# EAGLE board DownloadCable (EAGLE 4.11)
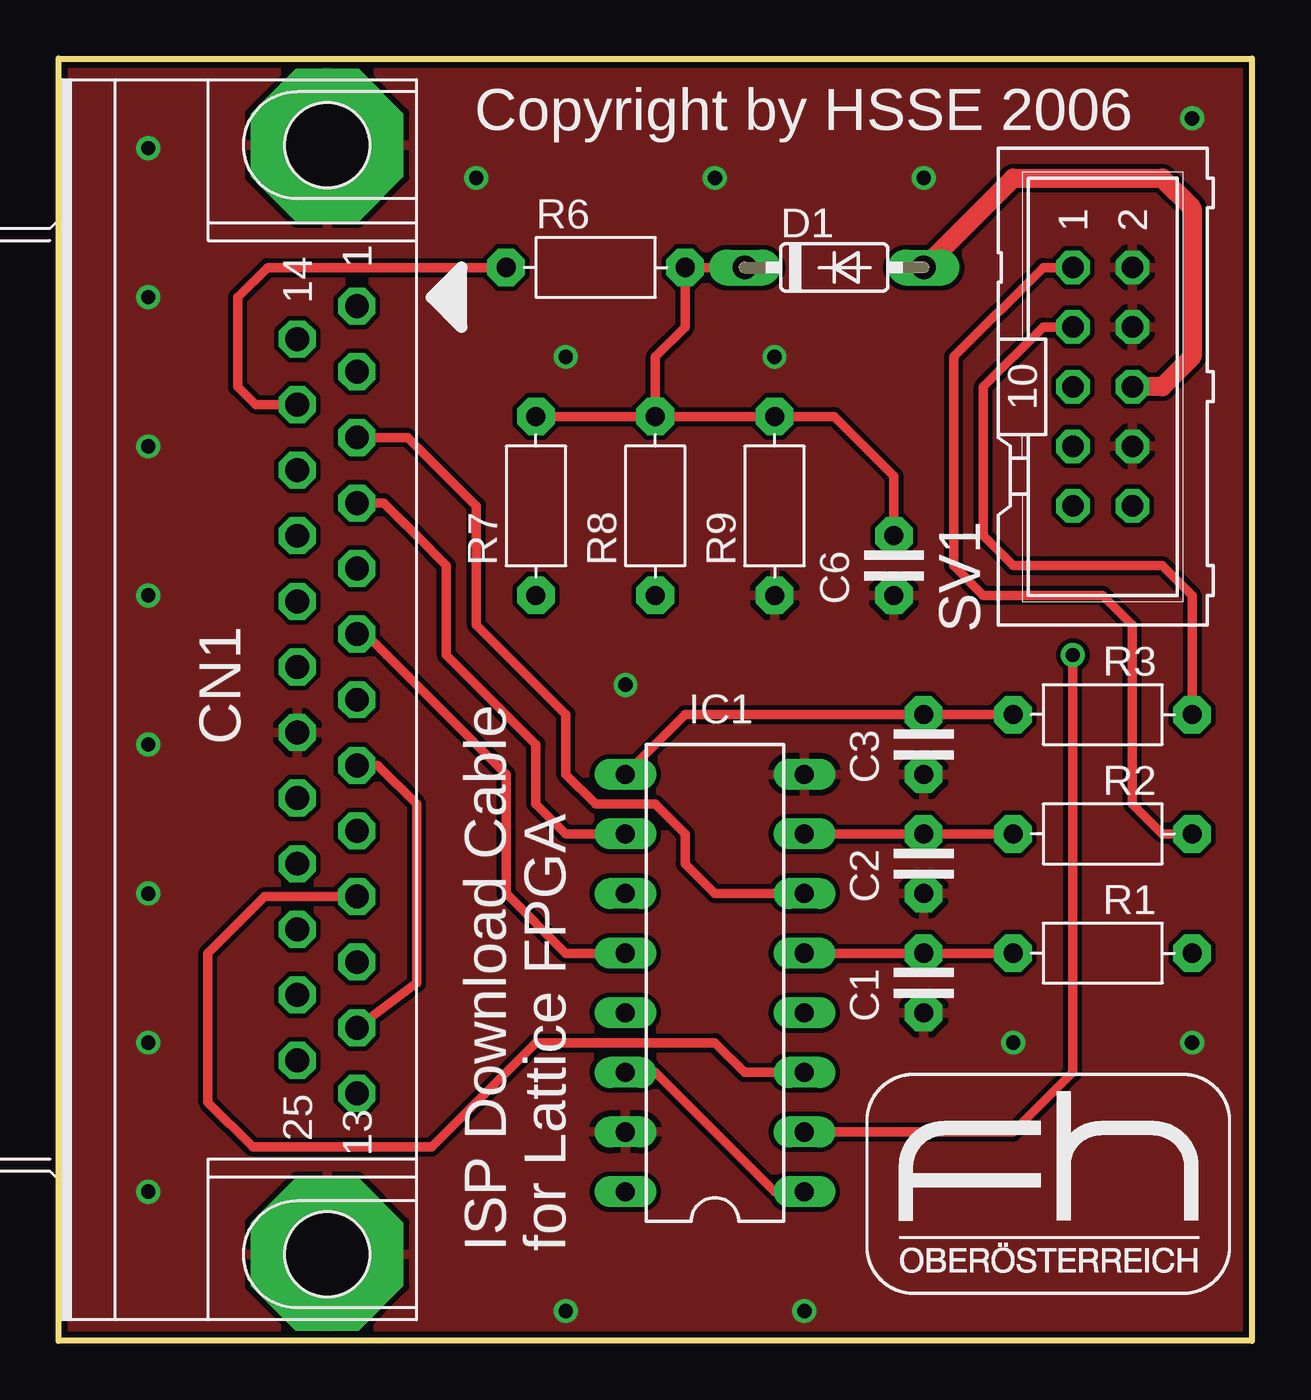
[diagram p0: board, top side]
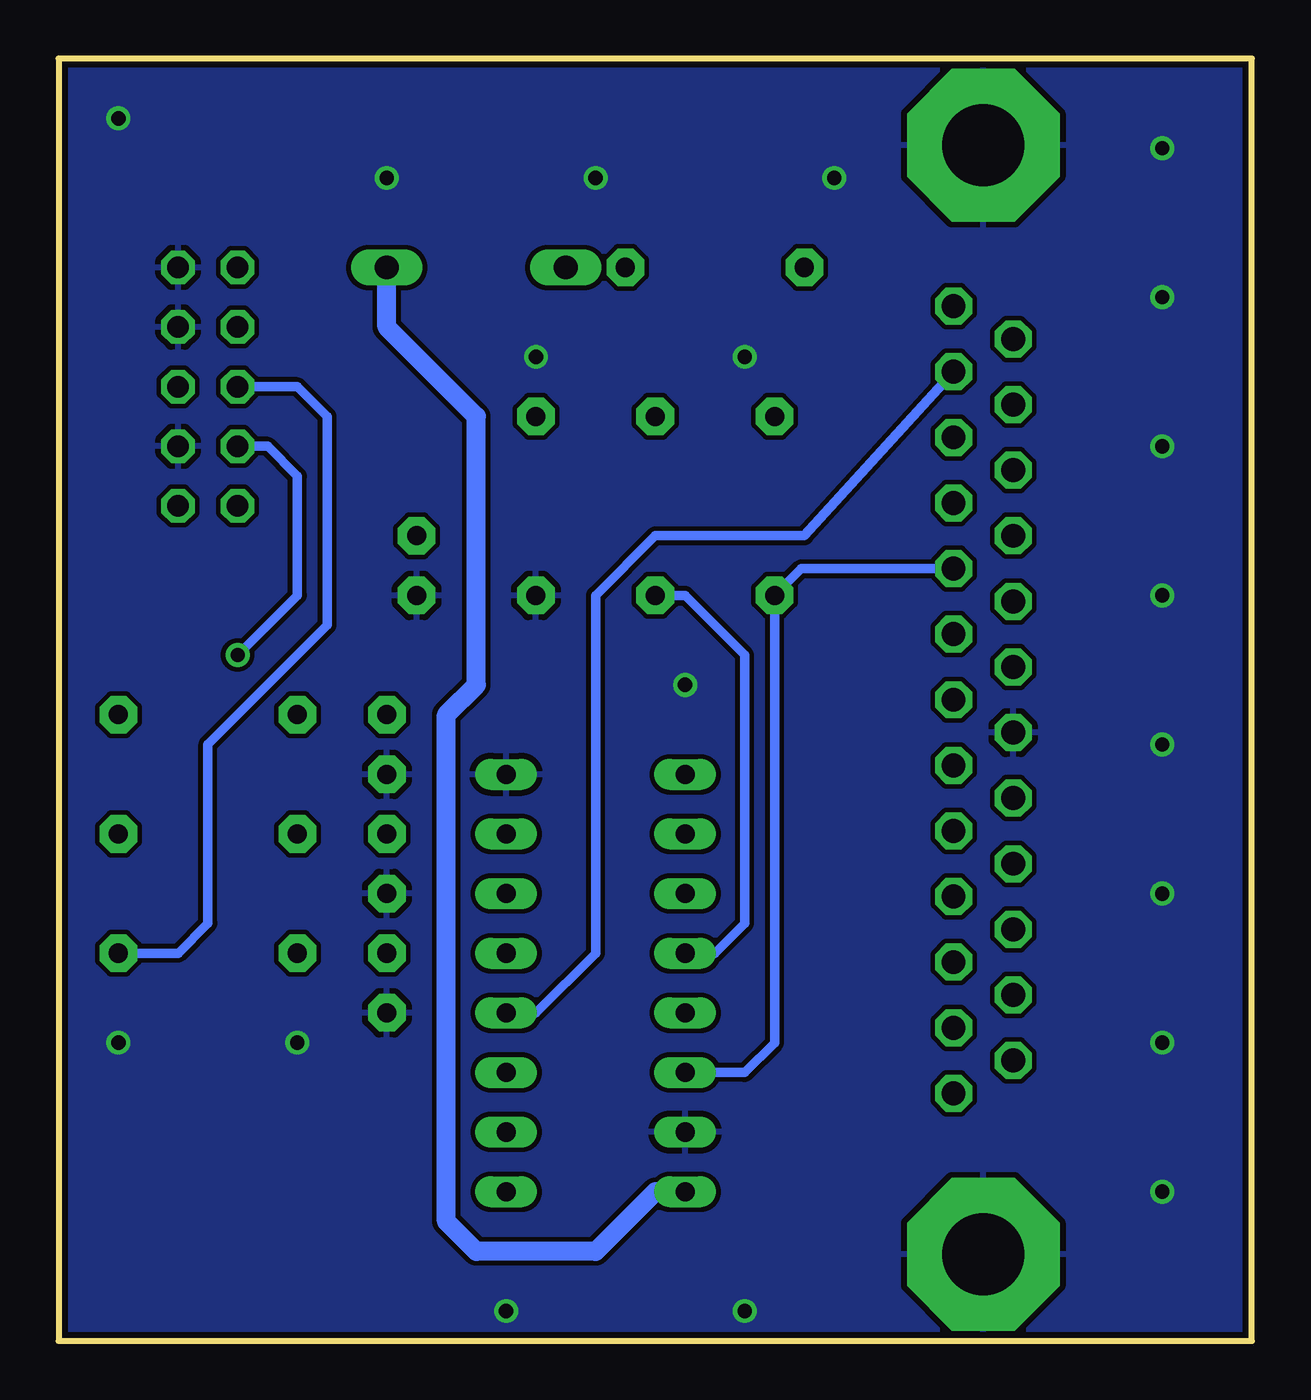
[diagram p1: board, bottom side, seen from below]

Size 50.8 x 54.61 mm. Coordinates in mm from the lower left corner, seen from the top.
Outline: 0,0 0,54.61 50.8,54.61 50.8,0 0,0
Copper layers (1*16): Top 0.035mm / dielectric 1.5mm / Bottom 0.035mm
Design rules "default": minimum track width 10mil, minimum drill 24mil, track to track 8mil, track to pad 8mil, pad to pad 8mil, via to via 8mil, smd to smd 0mil, copper to edge 10mil, drill to drill 8mil, minimum pad ring 10mil, minimum via ring 8mil, stop-mask expansion 4mil, vias tented up to drill 0mil, thermal gap 10mil

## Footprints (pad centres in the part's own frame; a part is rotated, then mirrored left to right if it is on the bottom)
C-2,5 = drill 0.813 pad 1.6 octagon: 1 -1.27,0; 2 1.27,0
D_25M/90 = drill 1.016 pad 1.575 octagon: 1 16.764,-1.27; 2 13.97,-1.27; 3 11.176,-1.27; 4 8.382,-1.27; 5 5.588,-1.27; 6 2.794,-1.27; 7 0,-1.27; 8 -2.794,-1.27; 9 -5.588,-1.27; 10 -8.382,-1.27; 11 -11.176,-1.27; 12 -13.97,-1.27; 13 -16.764,-1.27; 14 15.367,1.27; 15 12.573,1.27; 16 9.779,1.27; 17 6.985,1.27; 18 4.191,1.27; 19 1.397,1.27; 20 -1.397,1.27; 21 -4.191,1.27; 22 -6.985,1.27; 23 -9.779,1.27; 24 -12.573,1.27; 25 -15.367,1.27 | drill 3.5 pad 6.5 octagon: P$1 -23.622,0; P$2 23.622,0
DO35-7 = drill 1.016 long: A 3.81,0; C -3.81,0
DIL16 = drill 0.813 long: 1 -8.89,-3.81; 2 -6.35,-3.81; 3 -3.81,-3.81; 4 -1.27,-3.81; 5 1.27,-3.81; 6 3.81,-3.81; 7 6.35,-3.81; 8 8.89,-3.81; 9 8.89,3.81; 10 6.35,3.81; 11 3.81,3.81; 12 1.27,3.81; 13 -1.27,3.81; 14 -3.81,3.81; 15 -6.35,3.81; 16 -8.89,3.81
R-7,5 = drill 0.813 pad 1.6 octagon: 1 -3.81,0; 2 3.81,0
ML10 = drill 0.914 octagon: 1 -5.08,-1.27; 2 -5.08,1.27; 3 -2.54,-1.27; 4 -2.54,1.27; 5 0,-1.27; 6 0,1.27; 7 2.54,-1.27; 8 2.54,1.27; 9 5.08,-1.27; 10 5.08,1.27

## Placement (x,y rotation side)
C1  560p  [C-2,5]  36.83,15.24 270 top
C2  560p  [C-2,5]  36.83,20.32 270 top
C3  560p  [C-2,5]  36.83,25.4 270 top
C6  100n  [C-2,5]  35.56,33.02 270 top
CN1  [D_25M/90]  11.43,27.3 90 top
D1  [DO35-7]  33.02,45.72 0 top
IC1  74HC367N  [DIL16]  27.94,15.24 90 top
R1  100R  [R-7,5]  44.45,16.51 0 top
R2  100R  [R-7,5]  44.45,21.59 0 top
R3  100R  [R-7,5]  44.45,26.67 0 top
R6  220R  [R-7,5]  22.86,45.72 0 top
R7  10k  [R-7,5]  20.32,35.56 90 top
R8  10k  [R-7,5]  25.4,35.56 90 top
R9  1k  [R-7,5]  30.48,35.56 90 top
SV1  [ML10]  44.45,40.64 270 top

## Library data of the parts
C1-C3 C6 R1-R3 R6-R9 = discrete
CN1 = Con-pc2
D1 = diode
IC1 = 74xx-eu
SV1 = con-harting-ml

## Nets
+3V3: D1.A IC1.16 SV1.6
GND: C1.2 C2.2 C3.2 C6.2 CN1.20 CN1.P$1 CN1.P$2 IC1.8 IC1.15 R9.1 SV1.2 SV1.4 SV1.8
N$1: C6.1 D1.C R6.2 R7.2 R8.2 R9.2
N$2: CN1.10 IC1.3
N$3: CN1.8 CN1.12
N$4: CN1.2 IC1.4
N$5: CN1.6 IC1.12 R8.1
N$6: CN1.5 IC1.1 IC1.14 R7.1
N$7: CN1.3 IC1.6
N$8: CN1.4 IC1.10
N$9: CN1.15 R6.1
N$11: C1.1 IC1.5 R1.1
N$12: C2.1 IC1.7 R2.1
N$13: C3.1 IC1.9 R3.1
TCK: R2.2 SV1.1
TDI: R1.2 SV1.5
TDO: IC1.2 SV1.7
TMS: R3.2 SV1.3

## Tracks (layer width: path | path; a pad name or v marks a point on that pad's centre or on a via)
+3V3
  Top 0.813: SV1.6 46.99,40.64 48.26,41.91 48.26,48.26 46.99,49.53 40.64,49.53 D1.A
  Bottom 0.813: IC1.16 25.4,6.35 27.94,3.81 33.02,3.81 34.29,5.08 34.29,26.67 33.02,27.94 33.02,39.37 36.83,43.18 D1.A
GND  (via drill 0.61)
  other vias: 3.81,50.8 3.81,44.45 3.81,38.1 3.81,31.75 3.81,25.4 3.81,19.05 3.81,12.7 3.81,6.35 21.59,1.27 31.75,1.27 48.26,12.7 40.64,12.7 36.83,49.53 27.94,49.53 17.78,49.53 21.59,41.91 30.48,41.91 24.13,27.94 48.26,52.07
  pour Top: 0,0 0,54.61 50.8,54.61 50.8,0
  pour Bottom: 0,0 0,54.61 50.8,54.61 50.8,0
N$1
  Top 0.406: D1.C R6.2 26.67,43.18 25.4,41.91 R8.2 | C6.1 35.56,36.83 33.02,39.37 R9.2 R8.2 | R7.2 R8.2
N$2
  Top 0.406: IC1.3 29.21,11.43 27.94,12.7 20.32,12.7 15.88,8.26 8.26,8.26 6.35,10.16 6.35,16.51 7.62,17.78 | 7.62,17.78 8.13,18.29 | CN1.10 8.76,18.92 7.62,17.78
N$3
  Top 0.406: CN1.12 15.24,15.24 15.24,21.59 15.24,22.86 13.59,24.51 CN1.8
N$4
  Bottom 0.406: IC1.4 30.48,13.97 27.94,16.51 27.94,31.75 25.4,34.29 19.05,34.29 CN1.2
N$5
  Top 0.406: IC1.12 21.59,16.51 19.05,19.05 19.05,24.13 13.97,29.21 | 13.97,29.21 13.72,29.46 | CN1.6 13.08,30.1 13.97,29.21
  Bottom 0.406: R8.1 24.13,31.75 21.59,29.21 21.59,17.78 22.86,16.51 IC1.12
N$6
  Top 0.406: IC1.1 30.48,6.35 25.4,11.43 IC1.14
  Bottom 0.406: R7.1 19.81,32.26 | IC1.14 21.59,11.43 20.32,12.7 R7.1 | CN1.5 19.18,32.89 R7.1
N$7
  Top 0.406: IC1.6 27.94,19.05 26.67,20.32 26.67,21.59 25.4,22.86 22.86,22.86 21.59,24.13 21.59,26.67 17.78,30.48 17.78,35.56 14.86,38.48 CN1.3
N$8
  Top 0.406: IC1.10 21.59,21.59 20.32,22.86 20.32,25.4 16.51,29.21 16.51,33.02 15.24,34.29 | 15.24,34.29 14.48,35.05 | CN1.4 13.84,35.69 15.24,34.29
N$9
  Top 0.406: R6.1 8.89,45.72 7.62,44.45 7.62,40.64 8.38,39.88 CN1.15
N$11
  Top 0.406: IC1.5 C1.1 R1.1
N$12
  Top 0.406: IC1.7 C2.1 R2.1
N$13
  Top 0.406: IC1.9 26.67,26.67 C3.1 R3.1
TCK
  Top 0.406: R2.2 46.99,21.59 45.72,22.86 45.72,30.48 44.45,31.75 39.37,31.75 38.1,33.02 38.1,41.91 41.91,45.72 SV1.1
TDI
  Bottom 0.406: R1.2 45.72,16.51 44.45,17.78 44.45,25.4 39.37,30.48 39.37,39.37 40.64,40.64 SV1.5
TDO  (via drill 0.61)
  Top 0.406: IC1.2 40.64,8.89 43.18,11.43 v43.18,29.21
  Bottom 0.406: SV1.7 41.91,38.1 40.64,36.83 40.64,31.75 v43.18,29.21
TMS
  Top 0.406: R3.2 48.26,31.75 46.99,33.02 40.64,33.02 39.37,34.29 39.37,40.64 41.91,43.18 SV1.3

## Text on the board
tPlace: Copyright by HSSE 2006 | ISP Download Cable | for Lattice FPGA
